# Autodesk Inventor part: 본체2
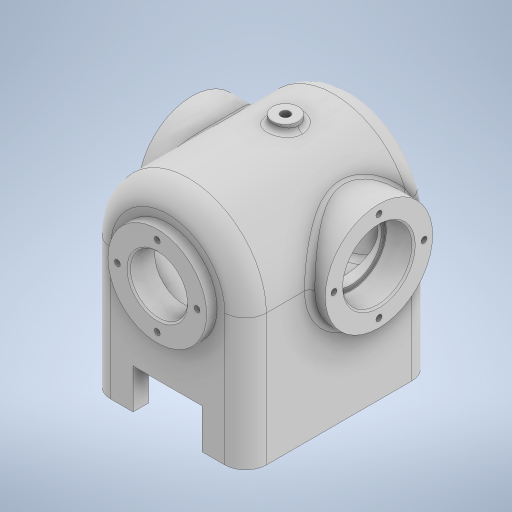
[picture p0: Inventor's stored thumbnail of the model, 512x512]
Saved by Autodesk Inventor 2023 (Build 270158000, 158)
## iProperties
Created: 2024-09
Part Number: 본체2
Material: 일반
Document SubType Name: Modeling
Designer: asung
Density: 1 g/cm^3
Appearance: 기본값
Author: asung
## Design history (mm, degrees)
sketch "스케치1"
  geometry: L1 (-45, -38)-(45, -38); L2 (45, -38)-(45, 38); L3 (45, 38)-(-45, 38); L4 (-45, 38)-(-45, -38); L5 (-45, -38)-(45, 38); L6 (45, -38)-(-45, 38); 3 further points
  constraints: 12 end point, 3 midpoint, 2 parallel, 1 horizontal, 1 perpendicular, 3 other
  dimensions: "d0" = 90 distance of L3.end L2.end; "d1" = 76 distance of L2.end L1.end
extrude "돌출1" new body sketch "스케치1" stored distance "d2" = 108; taper "d3" = 0 deg
sketch "스케치2"
  geometry: L1 (-45, 38)-(-45, -38) reference; L2 (-45, -38)-(45, -38) reference; L3 (45, -38)-(45, 38) reference; L4 (-20, -38)-(20, -38); L5 (20, -38)-(20, -15); L6 (20, -15)-(-20, -15); L7 (-20, -15)-(-20, -38); A1 r 45 centre (0, 38) between (45, 38) and (-45, 38) reference; 2 further points
  constraints: 8 end point, 2 parallel, 1 horizontal, 1 perpendicular, 1 point on line
  dimensions: "d4" = 40 distance of L6.end L5.end; "d5" = 23 distance of L5.end L4.end; "d6" = 25 distance between parallel lines of L1 L7
extrude "돌출2" cut sketch "스케치2" stored distance "d7" = 108; taper "d8" = 0 deg
feature "쉘1" dims "d9" = 9
sketch "스케치3"
  geometry: C1 r 45 at (0, 38); A1 r 36 centre (0, 38) between (36, 38) and (-36, 38) reference; 1 further point
  constraints: 1 centre point, 1 coincident
extrude "돌출3" join sketch "스케치3" distance "d10" = 108; taper "d11" = 0 deg
sketch "스케치4"
  geometry: L1 (-45, 38)-(-45, -38) reference; L2 (-45, -38)-(-20, -38) reference; L3 (-20, -38)-(-20, -15) reference; L4 (-20, -15)-(20, -15) reference; L5 (20, -15)-(20, -38) reference; L6 (20, -38)-(45, -38) reference; L7 (45, -38)-(45, 38) reference; C1 r 28.5 at (0, 38); A1 r 45 centre (0, 38) between (45, 38) and (-45, 38) reference; 1 further point
  constraints: 1 centre point, 1 coincident
  dimensions: "d12" = 57 diameter of C1
extrude "돌출4" join sketch "스케치4" distance "d13" = 6; taper "d14" = 0 deg
sketch "스케치5"
  geometry: L1 (-7, -45)-(-7, 45) reference; L2 (-7, 45)-(-15, 45) reference; L3 (-15, 45)-(-15, 54) reference; L4 (-15, 54)-(9.5, 54) reference; L5 (9.5, 54)-(9.5, 60) reference; L6 (9.5, 60)-(66.5, 60) reference; L7 (66.5, 60)-(66.5, 54) reference; L8 (66.5, 54)-(83, 54) reference; L9 (83, 54)-(83, -54) reference; L10 (83, -54)-(-15, -54) reference; L11 (-15, -54)-(-15, -45) reference; L12 (-15, -45)-(-7, -45) reference; L13 (66.5, 60)-(9.5, 60) reference; L14 (38, -54)-(-38, -54) reference; L15 (38, 60)-(38, -54); L16 (38, -54)-(38, 54) reference; L17 (38, -45)-(71, -45); L18 (74, -42)-(74, 42); L19 (71, 45)-(54.5, 45); L20 (54.5, 45)-(54.5, 60); A1 r 3 centre (71, -42) between (71, -45) and (74, -42); A2 r 3 centre (71, 42) between (74, 42) and (71, 45); 4 further points
  constraints: 10 end point, 4 perpendicular, 4 point on circle, 4 tangent, 2 centre point, 2 point on line, 1 equal radius, 1 horizontal, 1 midpoint
  dimensions: "d15" = 9 distance between parallel lines of L10 L17; "d16" = 9 distance between parallel lines of L18 L9; "d17" = 9 distance between parallel lines of L8 L19; "d18" = 16.5 distance from line of L16.end L20; "d19" = 3 radius of A1
revolve "회전1" sketch "스케치5" stored, may be unused: angle "d20" = 90 deg
chamfer "모따기1" distance "d21" = 1; stored, may be unused: second distance "d22" = 2, angle "d23" = 45 deg
node "작업 평면1"
sketch "스케치6"
  geometry: L1 (-38, -54)-(-38, 54) reference; L2 (66.5, 60)-(9.5, 60) reference; C1 r 31 at (38, -14); 1 further point
  constraints: 1 centre point
  dimensions: "d25" = 62 diameter of C1; "d26" = 76 distance from line of L1 C1.centre; "d27" = 74 distance from line of C1.centre L2
extrude "돌출5" join sketch "스케치6" stored distance "d28" = 6; taper "d29" = 0 deg
sketch "스케치7"
  geometry: C1 r 31 at (0, 0) reference; 2 further points
  constraints: 1 coincident
hole "구멍1" sketch "스케치7" at (0, 0) diameter "d30" = 35; stored, may be unused: countersink angle "d34" = 90 deg, drill point angle "d36" = 0 deg; dims "d31" = 6, "d32" = 40, "d33" = 16, "d35" = 50
sketch "스케치8"
  geometry: C1 r 31 at (0, 0) reference; 2 further points
  constraints: 1 coincident
hole "구멍2" sketch "스케치8" at (0, 0) diameter "d37" = 35; stored, may be unused: countersink angle "d41" = 90 deg, drill point angle "d43" = 0 deg; dims "d38" = 6, "d39" = 40, "d40" = 16, "d42" = 50
chamfer "모따기2" distance "d44" = 1; stored, may be unused: second distance "d45" = 2, angle "d46" = 45 deg
fillet "모깎기1" dims "d47" = 0.3
node "작업 평면2"
sketch "스케치9"
  geometry: L1 (-9, 9)-(-9, 71) reference; L2 (73.5, 114)-(16.5, 114) reference; C1 r 7.5 at (45, 40); 1 further point
  constraints: 1 centre point
  dimensions: "d49" = 15 diameter of C1; "d50" = 54 distance from line of L1 C1.centre; "d51" = 74 distance from line of L2 C1.centre
extrude "돌출6" join sketch "스케치9" stored distance "d52" = 10; taper "d53" = 0 deg
sketch "스케치10"
  geometry: C1 r 7.5 at (0, 0) reference; 2 further points
  constraints: 1 coincident
hole "구멍3" sketch "스케치10" at (0, 0) diameter "d54" = 5.1881; stored, may be unused: countersink angle "d58" = 90 deg, drill point angle "d60" = 0 deg; dims "d55" = 20, "d56" = 40, "d57" = 16, "d59" = 20
fillet "모깎기2" dims "d61" = 12
fillet "모깎기3" dims "d62" = 3
sketch "스케치11" dims "d63" = 46
  geometry: C1 r 28.5 at (0, 0) reference; C2 r 17.5 at (0, 0) reference; 3 further points
  constraints: 1 coincident, 1 vertical alignment, 2 other
hole "구멍4" sketch "스케치11" at (0, 23) diameter "d64" = 3.45873; stored, may be unused: countersink angle "d68" = 90 deg, drill point angle "d70" = 118 deg; dims "d65" = 8, "d66" = 4, "d67" = 2, "d69" = 10
sketch "스케치12" dims "d74" = 52
  geometry: C1 r 31 at (0, 0) reference; C2 r 21 at (0, 0) reference; 3 further points
  constraints: 1 coincident, 1 vertical alignment, 2 other
hole "구멍5" sketch "스케치12" at (0, 26) diameter "d75" = 3.45873; stored, may be unused: countersink angle "d79" = 90 deg, drill point angle "d81" = 118 deg; dims "d76" = 8, "d77" = 4, "d78" = 2, "d80" = 10
node "솔리드1"
mirror "미러1"
pattern_circular "원형 패턴1" dims angle "d72" = 360 deg
pattern_circular "원형 패턴2" dims angle "d83" = 360 deg
mirror "미러2"
node "투영된 루프1"
node "투영된 루프2"
node "투영된 루프3"
node "투영된 루프4"
node "절단 모서리 투영1"
feature "A9D066F2-1C7D-4E18-AEED-F7BC21143FA4" dims "d30" = 35, "d31" = 6, "d32" = 40, "d33" = 16, "d34" = 90 deg, "d35" = 50, "d36" = 0
other parameters: "d24" = 54, "d48" = -125
